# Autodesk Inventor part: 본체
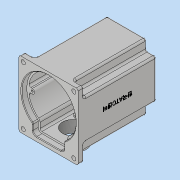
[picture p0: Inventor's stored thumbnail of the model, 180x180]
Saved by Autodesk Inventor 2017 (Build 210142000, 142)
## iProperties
Part Number: 본체
Material: 일반
Document SubType Name: Modeling
Designer: MRC
Density: 1 g/cm^3
Appearance: 기본값
Mass: 520.111 g
Surface Area: 1171.14 cm^2
Volume: 520.111 cm^3
Author: MRC
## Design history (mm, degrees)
sketch "스케치1"
  geometry: L1 (49, 55)-(-49, 55); L2 (-49, 55)-(-49, -55); L3 (-49, -55)-(49, -55); L4 (49, -55)-(49, 55); L5 (49, 55)-(-49, -55); L6 (-49, 55)-(49, -55); 1 further point
  constraints: 12 end point, 2 midpoint, 2 parallel, 1 horizontal, 1 perpendicular
  dimensions: "d0" = 98 distance of L3.end L2.end; "d1" = 110 distance of L2.end L1.end
extrude "돌출1" new body sketch "스케치1" distance "d2" = 10; taper "d3" = 0 deg
fillet "모깎기1" dims "d4" = 3
sketch "스케치2"
  geometry: L1 (46, 55)-(-46, 55) reference; L2 (33, -55)-(-33, -55); L3 (-33, -55)-(-33, 55); L4 (-33, 55)-(33, 55); L5 (33, 55)-(33, -55); L6 (33, -55)-(-33, 55); L7 (-33, -55)-(33, 55); 1 further point
  constraints: 12 end point, 2 midpoint, 2 parallel, 1 horizontal, 1 perpendicular, 1 point on line
  dimensions: "d5" = 66 distance of L3.end L4.end
extrude "돌출2" join sketch "스케치2" distance "d6" = 120; taper "d7" = 0 deg
sketch "스케치3"
  geometry: L1 (-49, -38)-(49, -38); L2 (49, -38)-(49, 28); L3 (49, 28)-(-49, 28); L4 (-49, 28)-(-49, -38); L5 (-49, -38)-(49, 28); L6 (49, -38)-(-49, 28); L7 (46, 55)-(-46, 55) reference; 3 further points
  constraints: 12 end point, 3 midpoint, 2 parallel, 1 horizontal, 1 perpendicular, 1 vertical alignment
  dimensions: "d8" = 98 distance of L3.end L2.end; "d9" = 66 distance of L2.end L1.end; "d10" = 27 distance between parallel lines of L7 L3
extrude "돌출3" join sketch "스케치3" distance "d11" = 120; taper "d12" = 0 deg
fillet "모깎기2" dims "d13" = 3
fillet "모깎기3" dims "d14" = 3
fillet "모깎기4" dims "d15" = 3
fillet "모깎기5" dims "d16" = 3
sketch "스케치4"
  geometry: L1 (-49, -41)-(-49, -52) reference; L2 (-46, -55)-(-36, -55) reference; C1 r 3.5 at (-42, -48); C2 r 3.5 at (-42, 48); C3 r 3.5 at (42, 48); C4 r 3.5 at (42, -48); 1 further point
  constraints: 4 centre point, 2 horizontal alignment, 2 vertical alignment
  dimensions: "d17" = 7 diameter of C1; "d18" = 7 diameter of C2; "d19" = 7 diameter of C3; "d20" = 7 diameter of C4; "d21" = 7 distance from line of L1 C1.centre; "d22" = 7 distance from line of L2 C1.centre; "d23" = 84 distance of C4.centre C1.centre; "d24" = 96 distance of C1.centre C2.centre
extrude "돌출4" cut sketch "스케치4" distance "d25" = 120; taper "d26" = 0 deg
sketch "스케치5"
  geometry: L1 (-27, -21)-(27, -21); L2 (27, -21)-(27, 33); L3 (27, 33)-(-27, 33); L4 (-27, 33)-(-27, -21); L5 (-27, -21)-(27, 33); L6 (27, -21)-(-27, 33); L7 (-30, -55)-(30, -55) reference; 3 further points
  constraints: 12 end point, 3 midpoint, 2 parallel, 1 horizontal, 1 perpendicular, 1 vertical alignment
  dimensions: "d27" = 54 distance of L3.end L2.end; "d28" = 54 distance of L2.end L1.end; "d29" = 61 distance from line of L7 point (0, 6)
extrude "돌출5" join sketch "스케치5" distance "d30" = 7; taper "d31" = 0 deg
fillet "모깎기6" dims "d32" = 3
fillet "모깎기7" dims "d33" = 3
sketch "스케치6"
  geometry: L1 (-46, 55)-(46, 55) reference; L2 (-23, -33.249)-(-23, -42); L3 (-20, -45)-(20, -45); L4 (23, -42)-(23, -33.249); L5 (0, 0)-(0, -65.918); A1 r 42 centre (0, 5) between (25.375, -28.468) and (-25.375, -28.468); A2 r 6 centre (29, -33.249) between (25.375, -28.468) and (23, -33.249); A3 r 6 centre (-29, -33.249) between (-23, -33.249) and (-25.375, -28.468); A4 r 3 centre (20, -42) between (20, -45) and (23, -42); A5 r 3 centre (-20, -42) between (-23, -42) and (-20, -45); 4 further points
  constraints: 12 point on circle, 8 end point, 8 tangent, 6 point on line, 5 centre point, 2 equal radius, 2 perpendicular, 2 vertical, 1 vertical alignment, 1 other
  dimensions: "d34" = 84 diameter of A1; "d35" = 50 distance from line of L1 A1.centre; "d36" = 46 distance of point (-23, -45) point (23, -45); "d37" = 50 distance from line of A1.centre L3; "d38" = 6 radius of A2; "d39" = 3 radius of A4
extrude "돌출6" cut sketch "스케치6" distance "d40" = 121; taper "d41" = 0 deg
sketch "스케치7"
  geometry: L1 (-23, -42)-(-23, -33.249) reference; L2 (20, -45)-(-20, -45) reference; L3 (23, -33.249)-(23, -42) reference; L4 (-26, -42)-(-26, -33.249); L5 (26, -33.249)-(26, -42); L6 (20, -48)-(-20, -48); A1 r 6 centre (29, -33.249) between (25.375, -28.468) and (23, -33.249) reference; A2 r 42 centre (0, 5) between (25.375, -28.468) and (-25.375, -28.468) reference; A3 r 6 centre (-29, -33.249) between (-23, -33.249) and (-25.375, -28.468) reference; A4 r 3 centre (-20, -42) between (-23, -42) and (-20, -45) reference; A5 r 3 centre (20, -42) between (20, -45) and (23, -42) reference; A6 r 6 centre (-20, -42) between (-26, -42) and (-20, -48); A7 r 3 centre (-29, -33.249) between (-26, -33.249) and (-27.188, -30.859); A8 r 45 centre (0, 5) between (27.188, -30.859) and (-27.188, -30.859); A9 r 3 centre (29, -33.249) between (27.188, -30.859) and (26, -33.249); A10 r 6 centre (20, -42) between (20, -48) and (26, -42); 1 further point
  constraints: 10 point on circle, 6 end point, 5 centre point, 7 other
  dimensions: "d42" = 3 distance between parallel lines of L2 L6
extrude "돌출7" cut sketch "스케치7" distance "d43" = 9; taper "d44" = 0 deg
chamfer "모따기1" distance "d45" = 1; stored, may be unused: second distance "d46" = 2, angle "d47" = 45 deg
sketch "스케치8"
  geometry: L1 (-46, 55)-(46, 55) reference; L2 (35.778, 1.006)-(41.81, 1.006); L3 (35.778, 8.994)-(41.81, 8.994); A1 r 36 centre (0, 5) between (36, 5) and (35.778, 1.006); A2 r 42 centre (0, 5) between (25.375, -28.468) and (-25.375, -28.468) reference; A3 r 4 centre (36, 5) between (36.222, 8.994) and (36.222, 1.006); 1 further point
  constraints: 9 point on circle, 4 end point, 2 centre point, 2 horizontal, 2 point on line, 1 horizontal alignment, 1 vertical alignment
  dimensions: "d48" = 72 diameter of A1; "d49" = 50 distance from line of L1 A1.centre; "d50" = 8 diameter of A3
extrude "돌출8" join sketch "스케치8" distance "d51" = 112; taper "d52" = 0 deg
fillet "모깎기8" dims "d53" = 3
fillet "모깎기9" dims "d54" = 3
sketch "스케치9"
  geometry: A1 r 4 centre (36, 5) between (35.778, 8.994) and (35.778, 1.006) reference; 2 further points
  constraints: 1 coincident
hole "구멍1" sketch "스케치9" at (36, 5) diameter "d55" = 3.242; stored, may be unused: countersink angle "d59" = 90 deg, drill point angle "d61" = 118 deg; dims "d56" = 7, "d57" = 4, "d58" = 2, "d60" = 9
sketch "스케치10"
  geometry: L1 (-46, 55)-(46, 55) reference; A1 r 21 centre (0, -6) between (-12.163, 11.119) and (12.163, 11.119); A2 r 15 centre (0, 25) between (11.584, 15.47) and (-11.584, 15.47); A3 r 3 centre (13.901, 13.565) between (11.584, 15.47) and (12.163, 11.119); A4 r 3 centre (-13.901, 13.565) between (-12.163, 11.119) and (-11.584, 15.47); 1 further point
  constraints: 8 point on circle, 4 centre point, 4 tangent, 2 vertical alignment, 1 equal radius
  dimensions: "d62" = 42 diameter of A1; "d63" = 61 distance from line of L1 A1.centre; "d64" = 30 diameter of A2; "d65" = 30 distance from line of L1 A2.centre; "d66" = 3 radius of A3 (derived)
extrude "돌출9" join sketch "스케치10" distance "d67" = 7; taper "d68" = 0 deg
fillet "모깎기10" dims "d69" = 3
sketch "스케치11"
  geometry: C1 r 17.5 at (0, -6); A1 r 21 centre (0, -6) between (-12.163, 11.119) and (12.163, 11.119) reference; 1 further point
  constraints: 1 centre point, 1 coincident
  dimensions: "d70" = 35 diameter of C1
extrude "돌출10" cut sketch "스케치11" distance "d71" = 10; taper "d72" = 0 deg
sketch "스케치12"
  geometry: A1 r 15 centre (0, 25) between (11.584, 15.47) and (-11.584, 15.47) reference; 2 further points
  constraints: 1 coincident
hole "구멍2" sketch "스케치12" at (0, 25) diameter "d73" = 19; stored, may be unused: countersink angle "d77" = 90 deg, drill point angle "d79" = 0 deg; dims "d74" = 7, "d75" = 22, "d76" = 7, "d78" = 10
fillet "모깎기11" dims "d80" = 3
fillet "모깎기12" dims "d81" = 0.3
chamfer "모따기2" distance "d82" = 1; stored, may be unused: second distance "d83" = 2, angle "d84" = 45 deg
sketch "스케치13"
  geometry: L1 (-27, 30)-(-27, -18) reference; L2 (24, 33)-(-24, 33) reference; C1 r 14 at (0, 6); 3 further points
  constraints: 2 midpoint, 1 centre point, 1 horizontal alignment, 1 vertical alignment
  dimensions: "d85" = 28 diameter of C1
extrude "돌출11" cut sketch "스케치13" stored distance "d86" = 10; taper "d87" = 0 deg
sketch "스케치14"
  geometry: C1 r 14 at (0, 6) reference; C2 r 16 at (0, 6); 1 further point
  constraints: 1 centre point, 1 coincident
  dimensions: "d88" = 32 diameter of C2
extrude "돌출12" cut sketch "스케치14" distance "d89" = 8.3; taper "d90" = 0 deg
fillet "모깎기13" dims "d91" = 0.3
chamfer "모따기3" distance "d92" = 0.8; stored, may be unused: second distance "d93" = 2, angle "d94" = 30 deg
sketch "스케치15"
  geometry: L1 (0, 0)-(92, 0) reference; C1 r 15 at (46, 89); 2 further points
  constraints: 1 centre point, 1 midpoint, 1 vertical alignment
  dimensions: "d95" = 30 diameter of C1; "d96" = 89 distance from line of L1 C1.centre
extrude "돌출13" join sketch "스케치15" distance "d97" = 5; taper "d98" = 0 deg
sketch "스케치16"
  geometry: L1 (0, 0)-(92, 0) reference; C1 r 22.5 at (46, 40); 2 further points
  constraints: 1 centre point, 1 midpoint, 1 vertical alignment
  dimensions: "d99" = 45 diameter of C1; "d100" = 40 distance from line of L1 C1.centre
extrude "돌출14" join sketch "스케치16" distance "d101" = 10; taper "d102" = 0 deg
fillet "모깎기14" dims "d103" = 3
sketch "스케치18"
  geometry: C1 r 15 at (20, 80) reference; C2 r 15 at (20, 80); 1 further point
  constraints: 1 centre point, 1 coincident
  dimensions: "d104" = 30 diameter of C2
extrude "돌출15" cut sketch "스케치18" distance "d105" = 5; taper "d106" = 0 deg
chamfer "모따기4" distance "d107" = 1; stored, may be unused: second distance "d108" = 2, angle "d109" = 30 deg
sketch "스케치20"
  geometry: C1 r 15 at (0, 0) reference; C2 r 10 at (0, 0); 1 further point
  constraints: 1 centre point, 1 coincident
  dimensions: "d110" = 20 diameter of C2
extrude "돌출16" cut sketch "스케치20" stored distance "d111" = 5; taper "d112" = 0 deg
sketch "스케치21"
  geometry: C1 r 22.5 at (0, 0) reference; 2 further points
  constraints: 1 coincident
hole "구멍3" sketch "스케치21" at (0, 0) diameter "d113" = 33.376; stored, may be unused: countersink angle "d117" = 90 deg, drill point angle "d119" = 0 deg; dims "d114" = 70, "d115" = 32, "d116" = 7, "d118" = 77.3
sketch "스케치22"
  geometry: L1 (104, 130)-(83, 130) reference; L2 (80, 13)-(80, 127) reference; 2 further points
  constraints: 1 other
  dimensions: "d120" = 65 distance from line of L1 point (47, 65); "d121" = 33 distance from line of L2 point (47, 65)
feature "엠보싱1" sketch "스케치22" dims "d5" = 66, "d122" = 0.5, "d123" = 0
chamfer "모따기5" distance "d124" = 1; stored, may be unused: second distance "d125" = 2, angle "d126" = 45 deg
node "솔리드1"
mirror "미러1"
mirror "미러2"
node "투영된 루프1"
